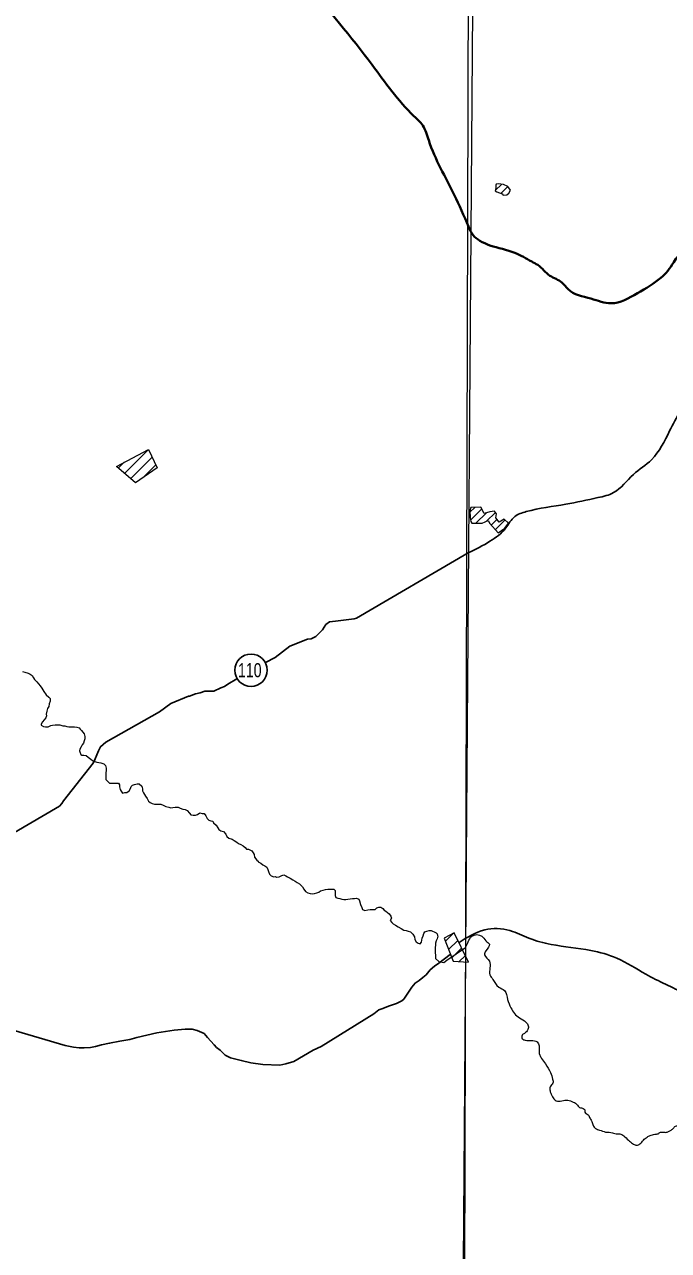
# Model space of a CAD drawing. Extents: x 553962 to 842807, y 8883888 to 9032388.
# Drawn here: x 616331 to 619526, y 8902976 to 8909058 of the extents above; entities that cross this region are included whole.
import ezdxf
from ezdxf.enums import TextEntityAlignment as Align

# ---------------------------------------------------------------- set-up
doc = ezdxf.new("R2010")
doc.units = 0
doc.header["$LTSCALE"] = 200
doc.layers.add('6', color=7, linetype='Continuous', lineweight=13)

msp = doc.modelspace()

# ---------------------------------------------------------------- linework, layer by layer
at = {"layer": '6'}
for p, q in [((618667.8, 8908235.7), (618697.2, 8908265)), ((618694.5, 8908219.9), (618729.1, 8908254.5)), ((616826.8, 8906831.1), (616945.6, 8906949.9)), ((616796.4, 8906857.3), (616825.3, 8906886.1)), ((616857.3, 8906805), (616964, 8906911.7)), ((616921.3, 8906812.4), (616982.4, 8906873.5)), ((618541.3, 8906638.8), (618565.2, 8906662.7)), ((618544.4, 8906599.4), (618599.8, 8906654.9)), ((618571.2, 8906583.9), (618623, 8906635.6)), ((618623.2, 8906593.4), (618667.4, 8906637.6)), ((618647.2, 8906575), (618675.6, 8906603.4)), ((618667.4, 8906552.7), (618715.2, 8906600.5)), ((618419.3, 8904510), (618459.5, 8904550.2)), ((618435.1, 8904469.2), (618480.5, 8904514.6)), ((618451, 8904428.5), (618499.1, 8904476.6)), ((618488.1, 8904409.1), (618517.7, 8904438.6))]:
    msp.add_line(p, q, dxfattribs=at)
for points in [[(618663, 8924716.1), (618558.3, 8909803.7), (618456.5, 8896026.7)], [(616320.5, 8905849.1), (616332.7, 8905845), (616349, 8905840.8), (616359.1, 8905835.6)], [(616359.1, 8905835.6), (616369.2, 8905828.4), (616376.3, 8905817.2), (616380.3, 8905808), (616391.4, 8905797.7), (616400.5, 8905786.5), (616408.5, 8905777.2), (616416.6, 8905765), (616426.7, 8905748.6), (616438.8, 8905733.2), (616450.9, 8905720.9), (616458, 8905713.8), (616457.9, 8905701.6), (616453.7, 8905687.3), (616451.6, 8905675.1), (616445.4, 8905664.9), (616441.2, 8905651.7), (616438.2, 8905636.4), (616439.5, 8905627.9), (616437, 8905619.4), (616419.4, 8905598.1), (616413.4, 8905587.8), (616413.3, 8905582.6), (616424.5, 8905575.4), (616435.6, 8905574.3), (616447.8, 8905574.3), (616461.1, 8905580.3), (616469.2, 8905581.7), (616483.5, 8905583.2), (616495.7, 8905584.1), (616505.6, 8905583.6), (616520.7, 8905578.7), (616530.4, 8905578.1), (616540.1, 8905575.7), (616551, 8905573.2), (616566.8, 8905573.2), (616579.5, 8905573.2), (616589.8, 8905572), (616602.6, 8905568.4), (616607.5, 8905563.1), (616614.5, 8905555.9), (616620.6, 8905547.7), (616626.6, 8905538.5), (616629.6, 8905526.2), (616630.5, 8905514), (616627.4, 8905503.8), (616623.2, 8905493.7), (616616.5, 8905485.2), (616611.7, 8905474.3), (616606.2, 8905463.3), (616604.4, 8905455.4), (616605, 8905450), (616611.1, 8905437.2), (616614.7, 8905433.6), (616624.9, 8905433.6), (616637.1, 8905432.5), (616646.2, 8905423.2), (616659.3, 8905414), (616668.4, 8905406.8), (616679.6, 8905402.6), (616689.8, 8905398.5), (616699.9, 8905397.4), (616710.1, 8905395.3), (616724.3, 8905390.1), (616732.4, 8905382.9)], [(616732.4, 8905382.9), (616735.3, 8905369.7), (616735.3, 8905359.5), (616735.2, 8905344.2), (616735, 8905325.9), (616734.9, 8905312.6), (616742, 8905304.4), (616752.1, 8905295.2), (616762.3, 8905294.1), (616773.5, 8905294.1), (616784.7, 8905294), (616796.9, 8905294.9), (616802.9, 8905285.7), (616802.8, 8905275.5), (616804.8, 8905262.3), (616810.8, 8905254.1), (616816.9, 8905244.9), (616828.1, 8905247.9), (616838.2, 8905247.8), (616850.5, 8905255.9), (616856.7, 8905268.1), (616860.8, 8905277.2), (616867, 8905285.3), (616877.2, 8905288.3), (616890.4, 8905291.3), (616900.6, 8905291.2), (616912.7, 8905279.9), (616915.7, 8905266.7), (616916.6, 8905256.5), (616921.7, 8905246.2), (616931.7, 8905229.9), (616939.8, 8905218.6), (616945.8, 8905205.3), (616954.9, 8905199.2), (616965, 8905194), (616976.2, 8905190.9), (616986.4, 8905190.8)], [(616986.4, 8905190.8), (616996.5, 8905190.7), (617006.7, 8905189.7), (617018.9, 8905185.5), (617032.1, 8905179.3), (617046.3, 8905175.1), (617056.4, 8905172), (617067.6, 8905173), (617078.8, 8905174.9), (617094.1, 8905174.8), (617103.2, 8905169.7), (617116.4, 8905165.5), (617127.6, 8905163.4), (617137.7, 8905158.2), (617148.8, 8905144.9), (617156.9, 8905136.7), (617167.1, 8905135.7), (617179.3, 8905135.6), (617188.5, 8905139.6), (617200.7, 8905146.6), (617212.9, 8905144.5), (617223.1, 8905143.4), (617231.1, 8905132.2), (617237.1, 8905118.9), (617245.2, 8905110.7), (617255.4, 8905107.6), (617265.5, 8905106.5), (617269.5, 8905097.3), (617281.7, 8905086), (617289.7, 8905073.7), (617295.8, 8905064.5), (617304.9, 8905058.4), (617319.1, 8905054.2), (617329.2, 8905040.9), (617334.2, 8905029.7), (617345.3, 8905022.4), (617361.6, 8905016.2), (617371.7, 8905010.1), (617383.8, 8905001.8), (617392.9, 8904995.7), (617404.1, 8904990.5), (617415.2, 8904984.3), (617425.3, 8904975.1), (617432.4, 8904966.9), (617442.6, 8904966.8), (617458.8, 8904958.6), (617464.8, 8904949.3), (617469.9, 8904940.1), (617472.8, 8904927.9), (617483.6, 8904913.2), (617490, 8904906.8), (617490, 8904904.7), (617503.1, 8904897.1), (617513.3, 8904888.9), (617523.5, 8904884.2), (617532.9, 8904877.9), (617539.1, 8904867), (617542.2, 8904856.1), (617546.9, 8904843.6), (617554.7, 8904834.2), (617568.8, 8904829.5), (617576.6, 8904831.1), (617581.2, 8904827.9), (617594.2, 8904829.3), (617607.5, 8904836.4)], [(617607.5, 8904836.4), (617617.7, 8904839.4), (617627.8, 8904835.2), (617635.9, 8904829.1), (617649.1, 8904822.9), (617662.3, 8904815.6), (617674.4, 8904808.4), (617684.6, 8904802.2), (617695.7, 8904795.1), (617709.9, 8904780.7), (617716.9, 8904769.4), (617725, 8904757.2), (617736.1, 8904751), (617748.3, 8904746.8), (617758.4, 8904745.8), (617769.6, 8904746.7), (617781.9, 8904749.7), (617791.1, 8904753.7), (617800.2, 8904759.7), (617812.5, 8904763.7), (617824.7, 8904767.7), (617835.9, 8904768.7), (617855.2, 8904768.6), (617865.4, 8904768.5), (617872.5, 8904761.3), (617872.4, 8904748.1), (617872.3, 8904737.9), (617876.3, 8904727.7), (617885.5, 8904723.5), (617895.6, 8904722.4), (617904.7, 8904718.3), (617914.9, 8904718.2), (617925.1, 8904718.2), (617935.3, 8904719.1), (617957.7, 8904723.1), (617967.8, 8904723), (617979, 8904724)], [(617979, 8904724), (617989.2, 8904719.8), (617993.2, 8904710.6), (617998.2, 8904693.3), (618004.1, 8904676.9), (618008.2, 8904667.7), (618020.3, 8904663.6), (618034.6, 8904665.5), (618046.8, 8904667.5), (618057, 8904667.4), (618071.2, 8904668.3), (618078.4, 8904675.4), (618089.6, 8904679.4), (618099.8, 8904679.4), (618108.9, 8904672.2), (618114.9, 8904664), (618124.1, 8904658.8), (618132.2, 8904652.7), (618140.2, 8904646.5), (618148.3, 8904635.3), (618151.3, 8904625.1), (618146.1, 8904612.9), (618153.2, 8904603.6), (618160.2, 8904596.5), (618171.4, 8904589.3), (618184.6, 8904582.1), (618199.8, 8904572.8), (618212.9, 8904564.6), (618225.1, 8904563.4), (618235.3, 8904560.3), (618245.4, 8904556.2), (618257.6, 8904545.9), (618265.6, 8904531.6), (618267.5, 8904519.4), (618274.6, 8904508.1), (618283.7, 8904500.9), (618293.8, 8904496.8), (618300, 8904505.9), (618303.1, 8904516.1), (618304.2, 8904526.3), (618309, 8904537.8), (618312.5, 8904548.5), (618317.6, 8904556.7), (618326.8, 8904561.1), (618339.4, 8904562.8), (618348.3, 8904562.8), (618355.5, 8904561.1), (618364.4, 8904557.5), (618373.3, 8904552.1), (618378.7, 8904546.7), (618380.5, 8904539.6), (618381.6, 8904536), (618378.4, 8904521.7), (618374.3, 8904511.6), (618370.2, 8904501.4), (618370.1, 8904491.2), (618369, 8904479), (618367.9, 8904468.8), (618370.7, 8904425), (618386.8, 8904409.6), (618410.9, 8904405.3), (618427, 8904416), (618519.7, 8904479.2)]]:
    msp.add_lwpolyline(points, dxfattribs=at)
for points in [[(618535.2, 8909853.3), (607574.3, 8909890.7), (607543.3, 8898835.3), (618504.2, 8898795.8)], [(618729.8, 8908254.2), (618707.5, 8908263.9), (618680.9, 8908266.8), (618672.1, 8908265.5), (618669.1, 8908261.2), (618669.9, 8908249.9), (618668.6, 8908238.7), (618667, 8908232.2), (618674.8, 8908227.9), (618687.9, 8908222.6), (618700.8, 8908217.5), (618706.7, 8908211.8), (618723.8, 8908212.4), (618734.6, 8908221.5), (618742.6, 8908236.5)], [(616786.7, 8906865.6), (616945.6, 8906950.1), (616989.1, 8906859.5), (616881.1, 8906784.5)], [(618595.3, 8906663), (618545.6, 8906662.6), (618541.1, 8906644.9), (618542, 8906612), (618545.6, 8906593), (618551, 8906583.5), (618601.6, 8906584.4), (618631.9, 8906597.1), (618640, 8906583.1), (618681.6, 8906537), (618714.5, 8906560), (618732.6, 8906584.9), (618710.5, 8906604.7), (618686.5, 8906589.8), (618669.4, 8906611.1), (618673, 8906630.5), (618662.6, 8906643.6), (618639.6, 8906640.9), (618612.5, 8906632.3)], [(618462.3, 8904551.7), (618413.4, 8904525.1), (618457.8, 8904411), (618533.6, 8904406.1)]]:
    msp.add_lwpolyline(points, close=True, dxfattribs=at)
at = {"layer": '6', "lineweight": 25}
for points in [[(618533.2, 8906436.6), (617978.2, 8906112.6), (617967, 8906109.6), (617874.3, 8906097.6), (617843.7, 8906095.6), (617826.3, 8906081.3), (617808.9, 8906055.9), (617776.2, 8906022.3), (617753.7, 8906010.2), (617735.4, 8906008.2), (617647.6, 8905973.7), (617574.1, 8905917.8), (617526.6, 8905893.4)], [(617384.3, 8905811.9), (617340.2, 8905785.8), (617322.9, 8905774.6), (617304.5, 8905767.5), (617270.8, 8905750.2), (617226, 8905750.3), (617202.5, 8905743.2), (617180.1, 8905738.2), (617149.5, 8905726), (617144.4, 8905726), (617057.7, 8905690.5), (617001.5, 8905648.8), (616735, 8905497.5), (616708.4, 8905475.2), (616698.2, 8905454.8), (616689.9, 8905434.4), (616681.7, 8905415.1), (616671.4, 8905393.7), (616524, 8905206.5), (616515.8, 8905193.3), (616504.6, 8905181.1), (616281, 8905049.1)], [(618442.8, 8904444.9), (618387.6, 8904401.3), (618365.2, 8904386.1), (618343.7, 8904367.8), (618323.2, 8904343.3), (618306.9, 8904331.1), (618288.5, 8904315.9), (618269.1, 8904302.7), (618252.7, 8904283.3), (618229.2, 8904247.7), (618212.8, 8904222.3), (618203.6, 8904215.2), (618177, 8904202), (618142.3, 8904189.8), (618104.6, 8904174.6), (618089.3, 8904169.5), (618064.8, 8904150.2), (617802.3, 8903987.7), (617762.5, 8903970.5), (617667.6, 8903914.6), (617626.8, 8903902.4), (617597.2, 8903896.4), (617513.6, 8903899.6), (617454.6, 8903907.9), (617406.7, 8903919.2), (617380.3, 8903925.3), (617352.8, 8903931.5), (617326.3, 8903944.8), (617302, 8903969.3), (617283.7, 8903982.5), (617271.5, 8903996.8), (617239, 8904033.6), (617221.8, 8904051.9), (617187.2, 8904067.3), (617162.8, 8904073.4), (617128.1, 8904074.5), (617074.1, 8904069.5), (616987.5, 8904055.4), (616887.5, 8904032.2), (616853.9, 8904022.1), (616803.9, 8904014), (616752.9, 8904003.9), (616713.2, 8903996.8), (616683.6, 8903987.7), (616658.1, 8903983.7), (616626.5, 8903981.7), (616602.1, 8903981.8), (616574.6, 8903984.9), (616532.8, 8903993.1), (616245.8, 8904077.2)]]:
    msp.add_lwpolyline(points, dxfattribs=at)
msp.add_circle((617454.9, 8905854.7), 80.3, dxfattribs=at)
at = {"layer": '6', "lineweight": 40}
msp.add_spline([(615971.7, 8911432.5), (616138.5, 8911227.2), (616313.3, 8911009), (616504.8, 8910771.9), (616895.5, 8910293.3), (617079.2, 8910062.8), (617725.5, 8909265.3), (618056.1, 8908857.7), (618263.2, 8908603.7), (618306.6, 8908556.9), (618336.6, 8908483.4), (618463.5, 8908212.8), (618533.7, 8908055.7), (618557.1, 8908012.3), (618590.5, 8907985.6), (618640.6, 8907962.2), (618764.1, 8907925.4), (618847.6, 8907882), (618877.7, 8907865.3), (618937.8, 8907811.8), (618997.9, 8907778.4), (619028, 8907745), (619141.5, 8907698.2), (619241.7, 8907674.8), (619372, 8907724.9), (619488.8, 8907801.8), (619552.3, 8907878.6), (619575.7, 8907905.4), (619599.1, 8907898.7), (619632.5, 8907871.9), (619679.2, 8907871.9), (619782.8, 8907918.7), (619872.9, 8907952.1), (619949.7, 8907952.1), (620026.6, 8907932.1), (620080, 8907908.7), (620120.1, 8907902), (620166.8, 8907932.1), (620233.6, 8907952.1), (620300.4, 8907958.8), (620363.9, 8907992.2), (620444, 8908052.4), (620517.5, 8908095.8), (620586.9, 8908115.3)], degree=3, dxfattribs=at)
at = {"layer": '6', "lineweight": 25}
for points in [[(618533.2, 8906436.6), (618640.7, 8906494.3), (618718.4, 8906559.7), (618763.3, 8906617), (618820.6, 8906641.5), (619016.9, 8906678.3), (619176.3, 8906711), (619254, 8906735.6), (619352.2, 8906825.5), (619442.1, 8906899.1), (619532.1, 8907042.2), (619630.2, 8907238.5), (619687.5, 8907398), (619720.2, 8907528.8), (619740.6, 8907635.2), (619765.2, 8907684.2), (619806, 8907741.5), (619834.7, 8907831.4), (619871.5, 8907884.6), (619957.3, 8907905), (620026.8, 8907892.8), (620094.6, 8907904)], [(618487.4, 8904504.8), (618614.5, 8904566.7), (618739.5, 8904562.9), (618834.2, 8904525), (618944, 8904494.7), (619141, 8904464.4), (619269.8, 8904426.5), (619413.7, 8904347), (619610.7, 8904248.5), (619898.6, 8904070.5), (620175.1, 8903918.9), (620288.7, 8903884.9), (620489.5, 8903873.5), (620815.2, 8903858.3), (621019.8, 8903831.8), (621319, 8903718.2), (621610.7, 8903631.1), (621785, 8903608.3), (621841.8, 8903604.6), (621917.5, 8903551.5), (622012.2, 8903479.6), (622084.2, 8903426.5), (622194.1, 8903396.2), (622315.3, 8903388.6)]]:
    msp.add_spline(points, degree=3, dxfattribs=at)
at = {"layer": '6'}
for points in [[(618519.7, 8904479.2), (618532.8, 8904506.8), (618550.3, 8904535.8), (618599.7, 8904535.8), (618620.1, 8904512.6), (618637.5, 8904495.1), (618620.1, 8904463.1), (618614.2, 8904442.8), (618637.5, 8904410.8), (618640.4, 8904378.8), (618640.4, 8904343.9), (618655, 8904320.7), (618684, 8904282.9), (618713.1, 8904265.4), (618727.6, 8904221.8), (618744.8, 8904180.8), (618762.3, 8904151.5), (618786.7, 8904131), (618818.9, 8904108.6), (618830.6, 8904091), (618828.7, 8904072.5), (618812.1, 8904053), (618800.4, 8904044.2), (618800.4, 8904026.6), (618815, 8904019.8), (618846.2, 8904017.8), (618874.5, 8904011), (618881.3, 8904002.2), (618885.2, 8903978.8), (618887.2, 8903945.6), (618897, 8903929), (618916.5, 8903901.7), (618940.9, 8903858.8), (618951.6, 8903826.6), (618952.6, 8903806.1), (618939.9, 8903788.6), (618938.9, 8903768.1), (618943.8, 8903752.4), (618951.6, 8903737.8), (618964.3, 8903721.2), (618988.7, 8903717.3), (619019.9, 8903722.2), (619047.2, 8903715.4), (619070.6, 8903701.7), (619085.3, 8903685.1), (619103.8, 8903681.2), (619110.6, 8903673.4), (619111.6, 8903661.7), (619127.2, 8903649.3), (619137, 8903630.8), (619146.7, 8903616.1), (619152.6, 8903596.6), (619164.3, 8903581.9), (619184.8, 8903573.2), (619214.1, 8903563.4)], [(619214.1, 8903563.4), (619248.2, 8903560.5), (619272.6, 8903554.6), (619289.2, 8903553.6), (619309.7, 8903540), (619333.1, 8903518.5), (619352.6, 8903503.8), (619369.2, 8903498), (619383.8, 8903504.8), (619402.4, 8903524.3), (619419.9, 8903539), (619435.5, 8903546.8), (619458, 8903552.7), (619474.6, 8903555.6), (619487.2, 8903562.4), (619506.8, 8903562.4), (619523.3, 8903564.4), (619537, 8903571.2), (619549.7, 8903581.9), (619561.4, 8903593.7), (619579, 8903591.7), (619602.4, 8903587.8), (619613.1, 8903587.8), (619630.7, 8903597.6), (619638.5, 8903604.4), (619648.2, 8903604.4), (619655.1, 8903595.6), (619667.8, 8903581.9), (619683.8, 8903571.2), (619694.6, 8903557.5), (619699.5, 8903545.8), (619709.2, 8903539), (619720, 8903533.1), (619740.4, 8903528.2), (619752.2, 8903520.4), (619759, 8903504.8), (619761.9, 8903487.2), (619771.7, 8903470.7), (619786.2, 8903450.4), (619800.9, 8903433.1), (619809.2, 8903423.3), (619815.2, 8903415), (619814.8, 8903409.7), (619805.4, 8903393.9), (619797.1, 8903375.4), (619797.9, 8903364.1), (619804.7, 8903355.4), (619816.7, 8903342.2), (619828.8, 8903330.9), (619839, 8903321.1), (619849.5, 8903308.7), (619861.2, 8903293.6), (619870.6, 8903279.3), (619878.6, 8903264.2), (619888, 8903248)]]:
    msp.add_spline(points, degree=3, dxfattribs=at)

# ---------------------------------------------------------------- texts
at = {"layer": '6', "width": 0.75}
msp.add_text('110', height=70, dxfattribs=at).set_placement((617448.6, 8905820), align=Align.CENTER)

doc.saveas('drawing.dxf')
